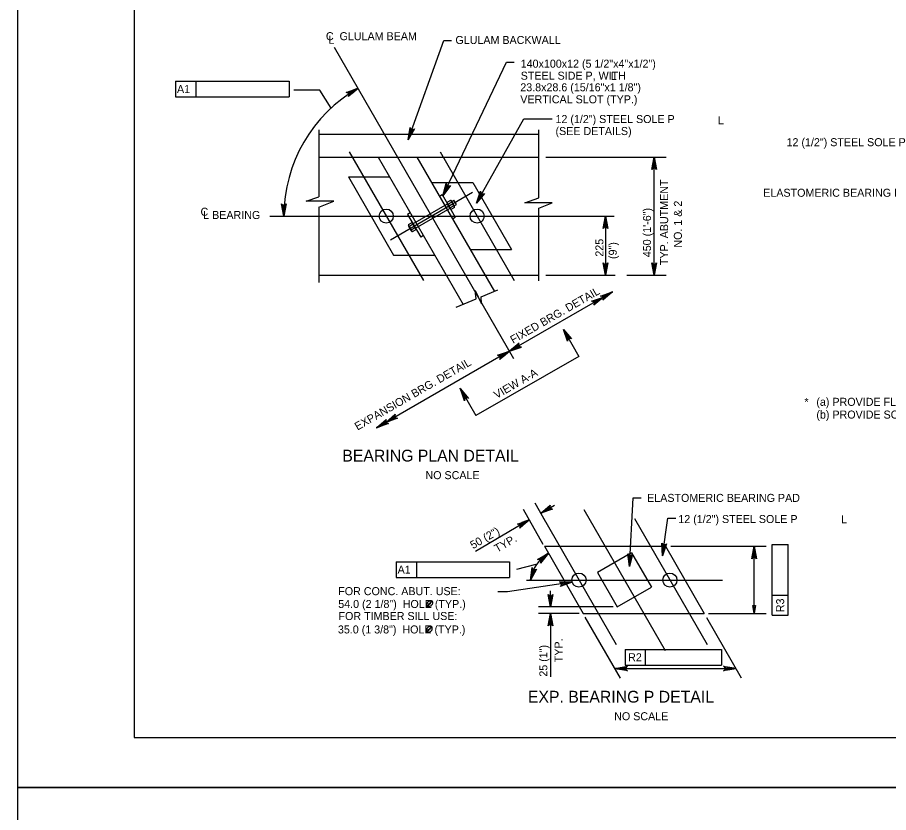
# Model space of a CAD drawing. Extents: x -13 to 81, y -176 to 0.
# Drawn here: x 0 to 13.06, y -132.38 to -120.46 of the extents above; entities that cross this region are included whole.
import ezdxf

# ---------------------------------------------------------------- set-up
doc = ezdxf.new("R2010")
doc.units = 0
for name, color, linetype in [('Level 1', 7, 'Continuous'), ('Level 3', 7, 'Continuous'), ('Level 4', 7, 'Continuous'), ('Level 5', 7, 'Continuous'), ('Level 52', 7, 'Continuous'), ('Level 62', 7, 'Continuous'), ('Level 63', 7, 'Continuous')]:
    doc.layers.add(name, color=color, linetype=linetype)

msp = doc.modelspace()

# ---------------------------------------------------------------- linework, layer by layer
at = {"layer": 'Level 1'}
msp.add_lwpolyline([(1.75, -131.25), (33.25, -131.25), (33.25, -110.75), (1.75, -110.75)], close=True, dxfattribs=at)
at = {"layer": 'Level 3'}
for p, q in [((4.751, -120.899), (7.441, -125.57)), ((4.522, -122.139), (4.522, -123.145)), ((7.821, -123.161), (7.821, -122.139)), ((4.522, -122.204), (7.821, -122.204)), ((4.976, -122.47), (6.087, -124.399)), ((6.339, -122.47), (7.45, -124.399)), ((4.522, -122.548), (7.821, -122.548)), ((5.408, -122.548), (6.683, -124.757)), ((5.99, -122.548), (7.152, -124.562)), ((4.964, -122.843), (5.641, -124.019)), ((4.964, -122.843), (5.585, -122.843)), ((6.21, -122.929), (6.83, -122.929)), ((6.83, -122.929), (7.409, -123.934)), ((4.332, -123.211), (4.522, -123.145)), ((5.593, -123.789), (6.824, -123.074)), ((6.329, -123.134), (6.369, -123.111)), ((6.369, -123.111), (6.566, -123.452)), ((7.607, -123.234), (7.821, -123.161)), ((4.743, -123.211), (4.332, -123.211)), ((4.522, -123.3), (4.743, -123.211)), ((4.522, -123.3), (4.522, -124.429)), ((5.931, -123.55), (6.449, -123.249)), ((5.969, -123.615), (6.487, -123.314)), ((6.491, -123.322), (6.446, -123.243)), ((6.492, -123.199), (6.447, -123.225)), ((6.463, -123.252), (6.508, -123.226)), ((6.493, -123.304), (6.538, -123.278)), ((6.552, -123.303), (6.507, -123.329)), ((6.554, -123.286), (6.509, -123.207)), ((6.513, -123.215), (6.545, -123.197)), ((6.582, -123.261), (6.545, -123.197)), ((6.55, -123.279), (6.582, -123.261)), ((8.018, -123.234), (7.607, -123.234)), ((7.821, -123.314), (8.018, -123.234)), ((7.821, -124.402), (7.821, -123.314)), ((5.891, -123.387), (5.851, -123.41)), ((5.851, -123.41), (6.047, -123.751)), ((6.524, -123.476), (6.566, -123.452)), ((5.91, -123.658), (5.864, -123.579)), ((5.866, -123.561), (5.91, -123.535)), ((5.926, -123.562), (5.881, -123.588)), ((5.973, -123.622), (5.927, -123.543)), ((5.956, -123.614), (5.911, -123.64)), ((5.926, -123.665), (5.97, -123.639)), ((6.089, -123.727), (6.047, -123.751)), ((6.79, -123.934), (7.409, -123.934)), ((5.641, -124.019), (6.249, -124.019)), ((4.522, -124.32), (6.43, -124.32)), ((6.43, -124.32), (7.013, -124.32)), ((7.013, -124.32), (7.821, -124.32)), ((8.495, -127.834), (9.712, -129.946)), ((7.868, -127.925), (8.979, -129.855)), ((9.256, -127.969), (10.342, -129.855)), ((7.905, -128.384), (8.484, -129.389)), ((7.905, -128.384), (9.72, -128.384)), ((9.72, -128.384), (10.298, -129.389)), ((9.211, -128.483), (8.7, -128.777)), ((9.211, -128.483), (9.507, -128.996)), ((8.7, -128.777), (8.995, -129.291)), ((8.995, -129.291), (9.507, -128.996)), ((8.484, -129.389), (10.298, -129.389))]:
    msp.add_line(p, q, dxfattribs=at)
for points in [[(7.847, -127.889), (7.991, -127.765), (7.984, -127.781), (7.983, -127.796), (7.988, -127.807), (7.996, -127.817), (8.008, -127.824), (8.026, -127.826), (7.847, -127.889), (8.008, -127.824), (7.996, -127.817), (7.847, -127.889), (7.988, -127.807), (7.983, -127.796), (7.847, -127.889), (7.984, -127.781)], [(7.675, -127.986), (7.532, -128.111), (7.539, -128.095), (7.539, -128.081), (7.535, -128.069), (7.527, -128.059), (7.514, -128.052), (7.497, -128.051), (7.675, -127.986), (7.514, -128.052), (7.527, -128.059), (7.675, -127.986), (7.535, -128.069), (7.539, -128.081), (7.675, -127.986), (7.539, -128.095)], [(9.672, -128.524), (9.664, -128.335), (9.672, -128.35), (9.683, -128.36), (9.695, -128.363), (9.708, -128.363), (9.721, -128.358), (9.733, -128.345), (9.672, -128.524), (9.721, -128.358), (9.708, -128.363), (9.672, -128.524), (9.695, -128.363), (9.683, -128.36), (9.672, -128.524), (9.672, -128.35)], [(11.047, -128.384), (11.082, -128.571), (11.072, -128.556), (11.059, -128.549), (11.047, -128.547), (11.034, -128.549), (11.022, -128.556), (11.012, -128.571), (11.047, -128.384), (11.022, -128.556), (11.034, -128.549), (11.047, -128.384), (11.047, -128.547), (11.059, -128.549), (11.047, -128.384), (11.072, -128.556)], [(7.965, -128.488), (7.844, -128.635), (7.849, -128.618), (7.847, -128.603), (7.84, -128.593), (7.831, -128.584), (7.817, -128.579), (7.8, -128.581), (7.965, -128.488), (7.817, -128.579), (7.831, -128.584), (7.965, -128.488), (7.84, -128.593), (7.847, -128.603), (7.965, -128.488), (7.849, -128.618)], [(9.181, -128.686), (9.156, -128.498), (9.165, -128.513), (9.177, -128.521), (9.19, -128.523), (9.202, -128.522), (9.215, -128.515), (9.226, -128.501), (9.181, -128.686), (9.215, -128.515), (9.202, -128.522), (9.181, -128.686), (9.19, -128.523), (9.177, -128.521), (9.181, -128.686), (9.165, -128.513)], [(7.692, -128.89), (7.72, -128.702), (7.724, -128.719), (7.734, -128.73), (7.745, -128.736), (7.758, -128.738), (7.772, -128.735), (7.786, -128.725), (7.692, -128.89), (7.772, -128.735), (7.758, -128.738), (7.692, -128.89), (7.745, -128.736), (7.734, -128.73), (7.692, -128.89), (7.724, -128.719)], [(7.995, -129.291), (7.96, -129.105), (7.97, -129.119), (7.983, -129.126), (7.995, -129.129), (8.008, -129.126), (8.02, -129.119), (8.03, -129.105), (7.995, -129.291), (8.02, -129.119), (8.008, -129.126), (7.995, -129.291), (7.995, -129.129), (7.983, -129.126), (7.995, -129.291), (7.97, -129.119)], [(7.995, -129.389), (8.03, -129.576), (8.02, -129.561), (8.008, -129.554), (7.995, -129.552), (7.983, -129.554), (7.97, -129.561), (7.96, -129.576), (7.995, -129.389), (7.97, -129.561), (7.983, -129.554), (7.995, -129.389), (7.995, -129.552), (8.008, -129.554), (7.995, -129.389), (8.02, -129.561)], [(8.961, -130.217), (9.147, -130.182), (9.133, -130.192), (9.125, -130.205), (9.123, -130.217), (9.125, -130.23), (9.133, -130.242), (9.147, -130.252), (8.961, -130.217), (9.133, -130.242), (9.125, -130.23), (8.961, -130.217), (9.123, -130.217), (9.125, -130.205), (8.961, -130.217), (9.133, -130.192)], [(10.775, -130.217), (10.589, -130.252), (10.603, -130.242), (10.611, -130.23), (10.613, -130.217), (10.611, -130.205), (10.603, -130.192), (10.589, -130.182), (10.775, -130.217), (10.603, -130.192), (10.611, -130.205), (10.775, -130.217), (10.613, -130.217), (10.611, -130.23), (10.775, -130.217), (10.603, -130.242)]]:
    msp.add_lwpolyline(points, dxfattribs=at)
for centre in [(5.531, -123.434), (6.894, -123.434), (8.421, -128.89), (9.784, -128.89)]:
    msp.add_circle(centre, 0.106, dxfattribs=at)
for centre, radius, start, end in [((6.46, -123.236), 0.0167, 141.316, 211.8561), ((6.46, -123.236), 0.0167, 211.8561, 278.7421), ((6.51, -123.259), 0.0477, 171.079, 248.979), ((6.504, -123.314), 0.0152, 137.4808, 282.5772), ((6.495, -123.216), 0.0167, 28.202, 98.7421), ((6.495, -123.216), 0.0167, 321.316, 28.202), ((6.49, -123.271), 0.0477, 351.079, 68.979), ((6.541, -123.293), 0.0152, 317.4808, 102.5772), ((5.879, -123.571), 0.0167, 141.2579, 211.7981), ((5.879, -123.571), 0.0167, 211.7981, 278.6841), ((5.913, -123.552), 0.0167, 28.1439, 98.6841), ((5.913, -123.552), 0.0167, 321.2579, 28.1439), ((5.909, -123.606), 0.0477, 351.021, 68.921), ((5.929, -123.595), 0.0477, 171.021, 248.921), ((5.923, -123.65), 0.0152, 137.4228, 282.5192), ((5.959, -123.629), 0.0152, 317.4228, 102.5192)]:
    msp.add_arc(centre, radius, start, end, dxfattribs=at)
at = {"layer": 'Level 4'}
for p, q in [((5.861, -122.292), (6.393, -120.803)), ((6.393, -120.803), (6.511, -120.803)), ((6.381, -123.13), (7.332, -121.124)), ((7.332, -121.124), (7.45, -121.124)), ((2.373, -121.411), (2.675, -121.411)), ((2.373, -121.411), (2.373, -121.647)), ((2.675, -121.411), (2.675, -121.647)), ((2.675, -121.411), (4.074, -121.411)), ((4.074, -121.411), (4.074, -121.647)), ((4.534, -121.548), (4.145, -121.548)), ((4.703, -121.815), (4.534, -121.548)), ((2.373, -121.647), (4.074, -121.647)), ((6.885, -123.242), (7.594, -121.975)), ((7.594, -121.975), (8.021, -121.975)), ((7.922, -122.548), (9.727, -122.548)), ((9.55, -124.32), (9.55, -122.548)), ((3.786, -123.434), (8.95, -123.434)), ((8.818, -123.434), (8.818, -124.32)), ((7.922, -124.32), (8.959, -124.32)), ((8.02, -124.32), (8.921, -124.32)), ((8.02, -124.32), (8.879, -124.32)), ((8.632, -124.32), (8.701, -124.32)), ((8.957, -124.32), (8.963, -124.32)), ((9.139, -124.32), (9.215, -124.32)), ((9.179, -124.32), (9.727, -124.32)), ((6.864, -124.55), (6.96, -124.75)), ((6.877, -124.675), (6.864, -124.55)), ((6.953, -124.644), (7.206, -124.54)), ((8.925, -124.571), (7.377, -125.459)), ((6.577, -124.801), (6.877, -124.675)), ((6.96, -124.75), (6.953, -124.644)), ((8.187, -125.132), (8.42, -125.536)), ((7.351, -125.474), (5.387, -126.608)), ((8.42, -125.536), (6.873, -126.424)), ((6.642, -126.023), (6.873, -126.424)), ((7.917, -128.01), (7.762, -127.737)), ((9.181, -128.686), (9.233, -127.657)), ((9.233, -127.657), (9.353, -127.657)), ((7.885, -128.356), (7.587, -127.831)), ((7.847, -127.889), (8.055, -127.769)), ((7.675, -127.986), (6.867, -128.462)), ((9.672, -128.524), (9.753, -127.96)), ((9.753, -127.96), (9.873, -127.96)), ((9.797, -128.384), (11.227, -128.384)), ((11.047, -129.389), (11.047, -128.384)), ((11.32, -128.356), (11.556, -128.356)), ((11.32, -129.115), (11.32, -128.356)), ((11.556, -129.417), (11.556, -128.356)), ((5.68, -128.615), (5.983, -128.615)), ((5.68, -128.615), (5.68, -128.851)), ((5.983, -128.615), (5.983, -128.851)), ((5.983, -128.615), (7.381, -128.615)), ((7.381, -128.615), (7.381, -128.851)), ((7.775, -128.656), (7.483, -128.729)), ((5.68, -128.851), (7.381, -128.851)), ((8.32, -128.923), (7.35, -129.064)), ((7.634, -128.89), (10.573, -128.89)), ((7.35, -129.064), (7.202, -129.064)), ((7.995, -129.291), (7.995, -129.051)), ((6.137, -129.296), (6.226, -129.197)), ((11.32, -129.417), (11.32, -129.115)), ((11.32, -129.115), (11.556, -129.115)), ((8.933, -129.291), (7.815, -129.291)), ((8.422, -129.389), (7.815, -129.389)), ((7.995, -129.389), (7.995, -130.338)), ((9.042, -130.358), (8.516, -129.444)), ((10.856, -130.358), (10.338, -129.458)), ((10.361, -129.389), (11.227, -129.389)), ((11.32, -129.417), (11.556, -129.417)), ((6.132, -129.68), (6.221, -129.582)), ((9.114, -129.929), (9.416, -129.929)), ((9.114, -129.929), (9.114, -130.166)), ((9.416, -129.929), (9.416, -130.166)), ((9.416, -129.929), (10.556, -129.929)), ((10.556, -129.929), (10.556, -130.166)), ((8.961, -130.217), (10.775, -130.217)), ((9.114, -130.166), (10.556, -130.166))]:
    msp.add_line(p, q, dxfattribs=at)
for points in [[(5.108, -121.518), (4.963, -121.641), (4.971, -121.625), (4.971, -121.61), (4.967, -121.598), (4.958, -121.588), (4.946, -121.581), (4.928, -121.58), (5.108, -121.518), (4.946, -121.581), (4.958, -121.588), (5.108, -121.518), (4.967, -121.598), (4.971, -121.61), (5.108, -121.518), (4.971, -121.625)], [(5.861, -122.292), (5.89, -122.105), (5.895, -122.121), (5.904, -122.133), (5.915, -122.139), (5.928, -122.141), (5.942, -122.138), (5.956, -122.128), (5.861, -122.292), (5.942, -122.138), (5.928, -122.141), (5.861, -122.292), (5.915, -122.139), (5.904, -122.133), (5.861, -122.292), (5.895, -122.121)], [(9.55, -122.548), (9.584, -122.735), (9.575, -122.721), (9.562, -122.713), (9.55, -122.711), (9.537, -122.713), (9.524, -122.721), (9.515, -122.735), (9.55, -122.548), (9.524, -122.721), (9.537, -122.713), (9.55, -122.548), (9.55, -122.711), (9.562, -122.713), (9.55, -122.548), (9.575, -122.721)], [(6.381, -123.13), (6.429, -122.947), (6.432, -122.964), (6.44, -122.976), (6.45, -122.984), (6.462, -122.987), (6.477, -122.986), (6.492, -122.977), (6.381, -123.13), (6.477, -122.986), (6.462, -122.987), (6.381, -123.13), (6.45, -122.984), (6.44, -122.976), (6.381, -123.13), (6.432, -122.964)], [(6.885, -123.242), (6.946, -123.062), (6.947, -123.079), (6.954, -123.092), (6.964, -123.1), (6.976, -123.104), (6.991, -123.104), (7.006, -123.096), (6.885, -123.242), (6.991, -123.104), (6.976, -123.104), (6.885, -123.242), (6.964, -123.1), (6.954, -123.092), (6.885, -123.242), (6.947, -123.079)], [(3.996, -123.434), (3.961, -123.248), (3.971, -123.262), (3.983, -123.27), (3.996, -123.272), (4.008, -123.27), (4.021, -123.262), (4.031, -123.248), (3.996, -123.434), (4.021, -123.262), (4.008, -123.27), (3.996, -123.434), (3.996, -123.272), (3.983, -123.27), (3.996, -123.434), (3.971, -123.262)], [(8.818, -123.434), (8.853, -123.621), (8.843, -123.606), (8.831, -123.599), (8.818, -123.597), (8.806, -123.599), (8.793, -123.606), (8.783, -123.621), (8.818, -123.434), (8.793, -123.606), (8.806, -123.599), (8.818, -123.434), (8.818, -123.597), (8.831, -123.599), (8.818, -123.434), (8.843, -123.606)], [(8.818, -124.32), (8.783, -124.134), (8.793, -124.148), (8.806, -124.155), (8.818, -124.158), (8.831, -124.155), (8.843, -124.148), (8.853, -124.134), (8.818, -124.32), (8.843, -124.148), (8.831, -124.155), (8.818, -124.32), (8.818, -124.158), (8.806, -124.155), (8.818, -124.32), (8.793, -124.148)], [(9.55, -124.32), (9.515, -124.134), (9.524, -124.148), (9.537, -124.155), (9.55, -124.158), (9.562, -124.155), (9.575, -124.148), (9.584, -124.134), (9.55, -124.32), (9.575, -124.148), (9.562, -124.155), (9.55, -124.32), (9.55, -124.158), (9.537, -124.155), (9.55, -124.32), (9.524, -124.148)], [(8.925, -124.571), (8.78, -124.694), (8.788, -124.678), (8.788, -124.663), (8.784, -124.652), (8.776, -124.642), (8.763, -124.635), (8.745, -124.633), (8.925, -124.571), (8.763, -124.635), (8.776, -124.642), (8.925, -124.571), (8.784, -124.652), (8.788, -124.663), (8.925, -124.571), (8.788, -124.678)], [(8.789, -124.648), (8.644, -124.771), (8.652, -124.755), (8.652, -124.741), (8.648, -124.729), (8.64, -124.719), (8.627, -124.712), (8.61, -124.71), (8.789, -124.648), (8.627, -124.712), (8.64, -124.719), (8.789, -124.648), (8.648, -124.729), (8.652, -124.741), (8.789, -124.648), (8.652, -124.755)], [(8.187, -125.132), (8.31, -125.276), (8.295, -125.268), (8.28, -125.268), (8.268, -125.272), (8.258, -125.28), (8.251, -125.293), (8.25, -125.31), (8.187, -125.132), (8.251, -125.293), (8.258, -125.28), (8.187, -125.132), (8.268, -125.272), (8.28, -125.268), (8.187, -125.132), (8.295, -125.268)], [(7.377, -125.459), (7.557, -125.398), (7.539, -125.396), (7.527, -125.389), (7.519, -125.379), (7.514, -125.367), (7.515, -125.353), (7.522, -125.337), (7.377, -125.459), (7.515, -125.353), (7.514, -125.367), (7.377, -125.459), (7.519, -125.379), (7.527, -125.389), (7.377, -125.459), (7.539, -125.396)], [(7.377, -125.459), (7.232, -125.581), (7.24, -125.565), (7.24, -125.551), (7.236, -125.539), (7.228, -125.529), (7.215, -125.522), (7.198, -125.52), (7.377, -125.459), (7.215, -125.522), (7.228, -125.529), (7.377, -125.459), (7.236, -125.539), (7.24, -125.551), (7.377, -125.459), (7.24, -125.565)], [(6.642, -126.023), (6.765, -126.167), (6.749, -126.16), (6.735, -126.159), (6.723, -126.164), (6.713, -126.172), (6.706, -126.185), (6.704, -126.202), (6.642, -126.023), (6.706, -126.185), (6.713, -126.172), (6.642, -126.023), (6.723, -126.164), (6.735, -126.159), (6.642, -126.023), (6.749, -126.16)], [(5.523, -126.527), (5.667, -126.404), (5.659, -126.419), (5.659, -126.434), (5.664, -126.446), (5.672, -126.456), (5.684, -126.463), (5.702, -126.464), (5.523, -126.527), (5.684, -126.463), (5.672, -126.456), (5.523, -126.527), (5.664, -126.446), (5.659, -126.434), (5.523, -126.527), (5.659, -126.419)], [(5.387, -126.608), (5.531, -126.485), (5.523, -126.501), (5.523, -126.515), (5.527, -126.527), (5.535, -126.537), (5.548, -126.544), (5.566, -126.545), (5.387, -126.608), (5.548, -126.544), (5.535, -126.537), (5.387, -126.608), (5.527, -126.527), (5.523, -126.515), (5.387, -126.608), (5.523, -126.501)]]:
    msp.add_lwpolyline(points, dxfattribs=at)
for points in [[(9.53, -122.667), (9.569, -122.667), (9.55, -122.548)], [(8.798, -123.552), (8.838, -123.552), (8.818, -123.434)], [(8.798, -124.202), (8.838, -124.202), (8.818, -124.32)], [(9.53, -124.202), (9.569, -124.202), (9.55, -124.32)], [(7.471, -125.382), (7.491, -125.416), (7.377, -125.459)], [(7.263, -125.501), (7.283, -125.536), (7.377, -125.459)], [(6.687, -126.15), (6.729, -126.127), (6.636, -126.014)], [(7.941, -127.811), (7.961, -127.846), (7.847, -127.889)], [(7.562, -128.029), (7.582, -128.064), (7.676, -127.987)], [(11.027, -128.504), (11.067, -128.504), (11.047, -128.384)], [(7.975, -129.171), (8.015, -129.171), (7.995, -129.291)], [(11.027, -129.269), (11.067, -129.269), (11.047, -129.389)], [(7.975, -129.509), (8.015, -129.509), (7.995, -129.389)], [(9.081, -130.197), (9.081, -130.237), (8.961, -130.217)], [(10.655, -130.197), (10.655, -130.237), (10.775, -130.217)]]:
    msp.add_lwpolyline(points, close=True, dxfattribs=at)
msp.add_arc((8.245, -128.975), 0.56, 119.9363, 171.2534, dxfattribs=at)
for points in [[(6.217, -129.207), (6.21, -129.202), (6.203, -129.2), (6.194, -129.199), (6.189, -129.199), (6.181, -129.201), (6.173, -129.205), (6.167, -129.208), (6.157, -129.216), (6.148, -129.227), (6.143, -129.237), (6.14, -129.246), (6.139, -129.255), (6.14, -129.262), (6.144, -129.273), (6.148, -129.278), (6.155, -129.284), (6.167, -129.287), (6.18, -129.286), (6.197, -129.279), (6.209, -129.268), (6.218, -129.256), (6.224, -129.242), (6.226, -129.228), (6.224, -129.218), (6.217, -129.207)], [(6.212, -129.592), (6.205, -129.586), (6.198, -129.584), (6.189, -129.584), (6.184, -129.584), (6.176, -129.586), (6.168, -129.589), (6.162, -129.592), (6.152, -129.601), (6.143, -129.612), (6.138, -129.622), (6.135, -129.631), (6.135, -129.64), (6.135, -129.647), (6.139, -129.657), (6.143, -129.663), (6.151, -129.669), (6.162, -129.672), (6.175, -129.671), (6.192, -129.663), (6.204, -129.653), (6.213, -129.64), (6.22, -129.627), (6.221, -129.612), (6.219, -129.603), (6.213, -129.592)]]:
    msp.add_spline(points, degree=3, dxfattribs=at)
at = {"layer": 'Level 5'}
for points in [[(4.995, -121.564), (5.016, -121.598), (5.108, -121.518)], [(4.02, -123.315), (3.98, -123.314), (3.996, -123.434)]]:
    msp.add_lwpolyline(points, close=True, dxfattribs=at)
msp.add_arc((6.204, -123.434), 2.208, 119.7701, 180, dxfattribs=at)
at = {"layer": 'Level 52'}
msp.add_lwpolyline([(8.32, -128.923), (8.14, -128.984), (8.153, -128.973), (8.159, -128.959), (8.159, -128.946), (8.155, -128.934), (8.146, -128.923), (8.13, -128.915), (8.32, -128.923), (8.146, -128.923), (8.155, -128.934), (8.32, -128.923), (8.159, -128.946), (8.159, -128.959), (8.32, -128.923), (8.153, -128.973)], dxfattribs=at)
at = {"layer": 'Level 62'}
msp.add_line((0, -132), (0, -132), dxfattribs=at)
at = {"layer": 'Level 63'}
for points in [[(0, -132), (34, -132), (34, -110), (0, -110)], [(0, -154), (34, -154), (34, -132), (0, -132)]]:
    msp.add_lwpolyline(points, close=True, dxfattribs=at)

# ---------------------------------------------------------------- texts
at = {"layer": 'Level 4'}
for s, height, p in [('C  GLULAM BEAM', 0.12, (4.626, -120.797)), ('L', 0.12, (4.663, -120.851)), ('GLULAM BACKWALL', 0.12, (6.568, -120.854)), ('140x100x12 (5 1/2"x4"x1/2")', 0.12, (7.547, -121.209)), ('STEEL SIDE P, WITH', 0.12, (7.547, -121.389)), ('L', 0.12, (8.899, -121.392)), ('23.8x28.6 (15/16"x1 1/8")', 0.12, (7.541, -121.563)), ('VERTICAL SLOT (TYP.)', 0.12, (7.541, -121.743)), ('12 (1/2") STEEL SOLE P', 0.12, (8.069, -122.039)), ('L', 0.12, (10.505, -122.056)), ('(SEE DETAILS)', 0.12, (8.069, -122.219)), ('12 (1/2") STEEL SOLE P', 0.12, (11.534, -122.386)), ('ELASTOMERIC BEARING PAD', 0.12, (11.184, -123.144)), ('C', 0.12, (2.746, -123.429)), ('L BEARING', 0.12, (2.786, -123.477)), ('*', 0.12, (11.802, -126.279)), ('(a) PROVIDE FLATNESS TOLERANCE IN ACCORDANCE WITH PUB. 408, SECTION 1105.03(p)', 0.12, (11.981, -126.278)), ('(b) PROVIDE SOLE PLATE IN ACCORDANCE WITH DM-4, D14.7.6.3.8dP', 0.12, (11.981, -126.469)), ('BEARING PLAN DETAIL', 0.17717, (4.872, -127.113)), ('NO SCALE', 0.12, (6.119, -127.377)), ('ELASTOMERIC BEARING PAD', 0.12, (9.443, -127.718)), ('12 (1/2") STEEL SOLE P', 0.12, (9.911, -128.035)), ('L', 0.12, (12.352, -128.037)), ('FOR CONC. ABUT. USE:', 0.12, (4.811, -129.116)), ('54.0 (2 1/8")  HOLE (TYP.)', 0.12, (4.811, -129.308)), ('FOR TIMBER SILL USE:', 0.12, (4.815, -129.489)), ('35.0 (1 3/8")  HOLE (TYP.)', 0.12, (4.806, -129.69)), ('EXP. BEARING P DETAIL', 0.17717, (7.655, -130.727)), ('L', 0.12, (10.005, -130.727)), ('NO SCALE', 0.12, (8.949, -130.991))]:
    msp.add_text(s, height=height, dxfattribs=at).set_placement(p)
for s, rotation, p in [('A1', 359.9382, (2.393, -121.589)), ('TYP. ABUTMENT', 90, (9.758, -124.168)), ('450 (1\'-6")', 90, (9.501, -124.05)), ('NO. 1 & 2', 90, (9.964, -123.907)), ('225', 90, (8.787, -124.042)), ('(9")', 90, (8.987, -124.077)), ('FIXED BRG. DETAIL', 29.9358, (7.433, -125.35)), ('EXPANSION BRG. DETAIL', 29.9358, (5.1, -126.65)), ('VIEW A-A', 29.9358, (7.187, -126.177)), ('50 (2")', 29.9358, (6.832, -128.429)), ('TYP.', 29.9358, (7.194, -128.48)), ('A1', 359.9382, (5.701, -128.793)), ('R3', 89.9382, (11.498, -129.372)), ('TYP.', 90, (8.175, -130.122)), ('25 (1")', 90, (7.947, -130.338)), ('R2', 359.9382, (9.158, -130.107))]:
    msp.add_text(s, height=0.12, rotation=rotation, dxfattribs=at).set_placement(p)

doc.saveas('drawing.dxf')
